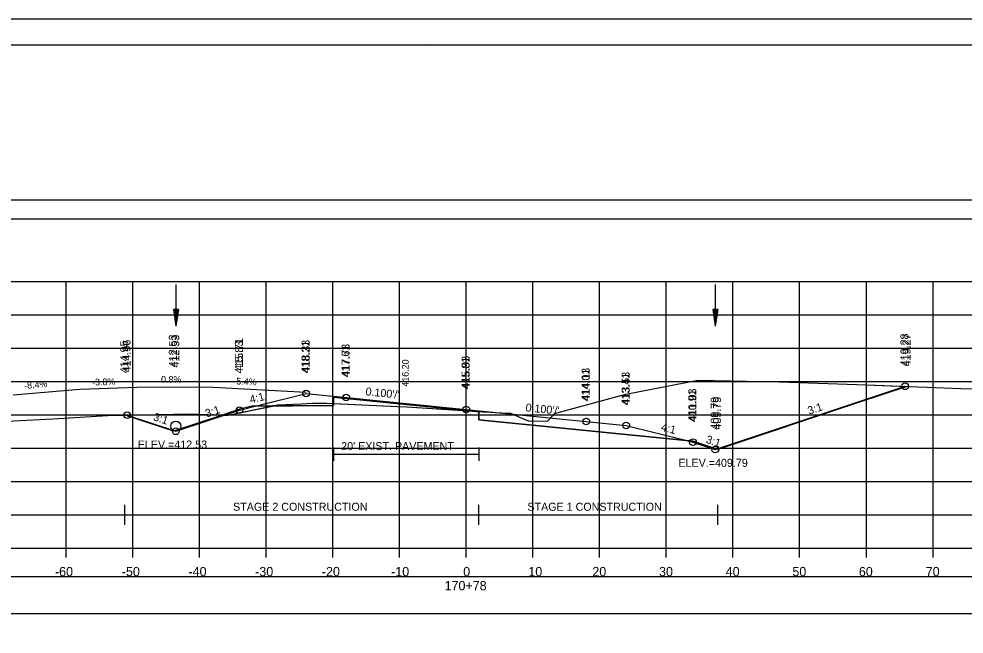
# Model space of a CAD drawing. Extents: x 1376273 to 1384221, y 378927 to 384592.
# Drawn here: x 1378523.5 to 1378665.3, y 381299.6 to 381391.9 of the extents above; entities that cross this region are included whole.
import ezdxf

# ---------------------------------------------------------------- set-up
doc = ezdxf.new("R2010")
doc.units = 0
for name, color, linetype in [('R_Alt Surface', 7, 'Continuous'), ('R_Axis', 7, 'Continuous'), ('R_Axis Annot', 7, 'Continuous'), ('R_Border', 7, 'Continuous'), ('R_Border Notes', 7, 'Continuous'), ('R_Contours', 7, 'Continuous'), ('R_Dimension', 7, 'Continuous'), ('R_Drive', 7, 'Continuous'), ('R_Exist Surface', 7, 'Continuous'), ('R_Fin Surface', 7, 'Continuous'), ('R_Grid', 7, 'Continuous'), ('R_No Plot', 7, 'Continuous'), ('R_Water', 7, 'Continuous'), ('R_Xsect Elev', 7, 'Continuous'), ('R_Xsect Slope', 7, 'Continuous'), ('T_Detection Zones', 7, 'Continuous')]:
    doc.layers.add(name, color=color, linetype=linetype)

msp = doc.modelspace()

# ---------------------------------------------------------------- linework, layer by layer
at = {"layer": 'R_Alt Surface'}
for points in [[(1378559.2, 381333.86), (1378570.72, 381333.98), (1378570.73, 381335.14), (1378590.64, 381333.15), (1378592.53, 381332.96), (1378592.54, 381331.8), (1378623.51, 381328.7)], [(1378570.73, 381327.61), (1378570.73, 381325.61)], [(1378592.53, 381327.61), (1378592.53, 381325.61)], [(1378570.73, 381326.61), (1378592.53, 381326.61)]]:
    msp.add_lwpolyline(points, dxfattribs=at)
at = {"layer": 'R_Axis'}
for p, q in [((1378440.64, 381312.51), (1378740.64, 381312.51)), ((1378530.64, 381311.11), (1378530.64, 381312.51)), ((1378540.64, 381311.11), (1378540.64, 381312.51)), ((1378550.64, 381311.11), (1378550.64, 381312.51)), ((1378560.64, 381311.11), (1378560.64, 381312.51)), ((1378570.64, 381311.11), (1378570.64, 381312.51)), ((1378580.64, 381311.11), (1378580.64, 381312.51)), ((1378590.64, 381311.11), (1378590.64, 381312.51)), ((1378600.64, 381311.11), (1378600.64, 381312.51)), ((1378610.64, 381311.11), (1378610.64, 381312.51)), ((1378620.64, 381311.11), (1378620.64, 381312.51)), ((1378630.64, 381311.11), (1378630.64, 381312.51)), ((1378640.64, 381311.11), (1378640.64, 381312.51)), ((1378650.64, 381311.11), (1378650.64, 381312.51)), ((1378660.64, 381311.11), (1378660.64, 381312.51))]:
    msp.add_line(p, q, dxfattribs=at)
at = {"layer": 'R_Axis Annot'}
for points in [[(1378439.67, 381361.89), (1378741.48, 381361.89), (1378741.48, 381364.71), (1378439.67, 381364.71)], [(1378439.67, 381302.71), (1378741.48, 381302.71), (1378741.48, 381308.24), (1378439.67, 381308.24)]]:
    msp.add_lwpolyline(points, close=True, dxfattribs=at)
at = {"layer": 'R_Border'}
for p, q in [((1378432.64, 381387.97), (1378748.82, 381387.97)), ((1378585.16, 381387.71), (1378585.16, 381387.71)), ((1378585.16, 381387.71), (1378585.16, 381387.71))]:
    msp.add_line(p, q, dxfattribs=at)
at = {"layer": 'R_Contours'}
msp.add_lwpolyline([(1378592.53, 381333.02), (1378593.11, 381332.98), (1378593.53, 381332.95), (1378593.53, 381332.95), (1378595.74, 381332.81), (1378595.95, 381332.8), (1378597.27, 381332.75), (1378598.87, 381332.04), (1378599.91, 381331.59), (1378600.07, 381331.59), (1378602.84, 381331.56), (1378602.95, 381331.69), (1378603.88, 381332.73), (1378614.58, 381335.62), (1378625.38, 381337.71), (1378637.6, 381337.44), (1378650.65, 381337.01), (1378656.78, 381336.78), (1378649.46, 381334.34), (1378628.36, 381327.3), (1378628.35, 381327.3), (1378624.64, 381328.54), (1378624.63, 381328.54), (1378624.62, 381328.54), (1378592.54, 381331.75)], close=True, dxfattribs=at)
at = {"layer": 'R_Dimension'}
for p, q in [((1378539.45, 381316.03), (1378539.45, 381319.03)), ((1378592.53, 381316.03), (1378592.53, 381319.03)), ((1378628.36, 381316.03), (1378628.36, 381319.03)), ((1378539.45, 381317.53), (1378628.36, 381317.53))]:
    msp.add_line(p, q, dxfattribs=at)
at = {"layer": 'R_Drive'}
for p, q in [((1378532.66, 381336.29), (1378522.7, 381335.44)), ((1378542.66, 381336.67), (1378532.66, 381336.29)), ((1378552.66, 381336.59), (1378542.66, 381336.67)), ((1378566.64, 381335.84), (1378552.66, 381336.59))]:
    msp.add_line(p, q, dxfattribs=at)
at = {"layer": 'R_Exist Surface'}
msp.add_lwpolyline([(1378520.85, 381331.49), (1378528.61, 381331.93), (1378536.82, 381332.41), (1378546.76, 381332.61), (1378548.88, 381332.64), (1378550.44, 381332.62), (1378554.87, 381332.44), (1378554.87, 381332.44), (1378561.82, 381333.88), (1378562.37, 381334.01), (1378565.9, 381334.17), (1378567.48, 381334.25), (1378567.58, 381334.25), (1378569.73, 381334.24), (1378580.33, 381333.77), (1378581.7, 381333.71), (1378593.11, 381332.98), (1378593.53, 381332.95), (1378593.53, 381332.95), (1378595.74, 381332.81), (1378595.95, 381332.8), (1378597.27, 381332.75), (1378598.87, 381332.04), (1378599.91, 381331.59), (1378600.07, 381331.59), (1378602.84, 381331.56), (1378602.95, 381331.69), (1378603.88, 381332.73), (1378614.58, 381335.62), (1378625.38, 381337.71), (1378637.6, 381337.44), (1378650.65, 381337.01), (1378664.85, 381336.48), (1378674.4, 381336.28)], dxfattribs=at)
at = {"layer": 'R_Fin Surface'}
msp.add_lwpolyline([(1378539.79, 381332.47), (1378547.09, 381330.04), (1378556.64, 381333.22), (1378559.2, 381333.86), (1378566.64, 381335.72), (1378572.64, 381335.12), (1378590.64, 381333.32), (1378608.64, 381331.52), (1378614.64, 381330.92), (1378623.51, 381328.7), (1378624.64, 381328.42), (1378627.99, 381327.3), (1378649.12, 381334.35), (1378656.46, 381336.79)], dxfattribs=at)
at = {"layer": 'R_Grid'}
for p, q in [((1378440.64, 381352.51), (1378740.64, 381352.51)), ((1378530.64, 381312.51), (1378530.64, 381352.51)), ((1378540.64, 381312.51), (1378540.64, 381352.51)), ((1378550.64, 381312.51), (1378550.64, 381352.51)), ((1378560.64, 381312.51), (1378560.64, 381352.51)), ((1378570.64, 381312.51), (1378570.64, 381352.51)), ((1378580.64, 381312.51), (1378580.64, 381352.51)), ((1378590.64, 381312.51), (1378590.64, 381352.51)), ((1378600.64, 381312.51), (1378600.64, 381352.51)), ((1378610.64, 381312.51), (1378610.64, 381352.51)), ((1378620.64, 381312.51), (1378620.64, 381352.51)), ((1378630.64, 381312.51), (1378630.64, 381352.51)), ((1378640.64, 381312.51), (1378640.64, 381352.51)), ((1378650.64, 381312.51), (1378650.64, 381352.51)), ((1378660.64, 381312.51), (1378660.64, 381352.51)), ((1378440.64, 381347.51), (1378740.64, 381347.51)), ((1378440.64, 381342.51), (1378740.64, 381342.51)), ((1378440.64, 381337.51), (1378740.64, 381337.51)), ((1378440.64, 381332.51), (1378740.64, 381332.51)), ((1378440.64, 381327.51), (1378740.64, 381327.51)), ((1378440.64, 381322.51), (1378740.64, 381322.51)), ((1378440.64, 381317.51), (1378740.64, 381317.51)), ((1378440.64, 381312.51), (1378740.64, 381312.51))]:
    msp.add_line(p, q, dxfattribs=at)
at = {"layer": 'R_No Plot'}
msp.add_line((1378420.24, 381391.86), (1378753.57, 381391.86), dxfattribs=at)
for points in [[(1378420.23, 381391.86), (1378753.57, 381391.86), (1378753.57, 381178.53), (1378420.23, 381178.53)], [(1378666.56, 381387.97), (1378666.56, 381378.09), (1378702.29, 381378.09), (1378702.29, 381375.17), (1378725.49, 381375.17), (1378725.49, 381350.84), (1378748.82, 381350.84), (1378748.82, 381182.51), (1378432.64, 381182.51), (1378432.64, 381387.97)]]:
    msp.add_lwpolyline(points, close=True, dxfattribs=at)
msp.add_lwpolyline([(1378558.5, 381333.81), (1378570.72, 381333.93), (1378570.73, 381335.26), (1378590.64, 381333.27), (1378592.53, 381333.08), (1378592.54, 381331.75), (1378624.62, 381328.54)], dxfattribs=at)
for centre in [(1378656.46, 381336.79), (1378566.64, 381335.72), (1378572.64, 381335.12), (1378539.79, 381332.47), (1378556.64, 381333.22), (1378590.64, 381333.32), (1378608.64, 381331.52), (1378614.64, 381330.92), (1378547.09, 381330.04), (1378547.09, 381330.04), (1378624.64, 381328.42), (1378627.99, 381327.3), (1378627.99, 381327.3)]:
    msp.add_circle(centre, 0.5, dxfattribs=at)
at = {"layer": 'R_Water'}
for p, q in [((1378547.09, 381352.04), (1378547.09, 381345.79)), ((1378627.99, 381352.04), (1378627.99, 381345.79)), ((1378546.72, 381348.29), (1378547.09, 381345.79)), ((1378547.47, 381348.29), (1378546.72, 381348.29)), ((1378546.78, 381348.29), (1378547.09, 381346.21)), ((1378546.84, 381348.29), (1378547.09, 381346.64)), ((1378546.9, 381348.29), (1378547.09, 381347.05)), ((1378546.97, 381348.29), (1378547.09, 381347.48)), ((1378547.03, 381348.29), (1378547.09, 381347.89)), ((1378547.47, 381348.29), (1378547.09, 381345.79)), ((1378547.21, 381348.29), (1378547.09, 381347.48)), ((1378547.34, 381348.29), (1378547.09, 381346.64)), ((1378547.4, 381348.29), (1378547.09, 381346.21)), ((1378547.28, 381348.29), (1378547.09, 381347.05)), ((1378547.15, 381348.29), (1378547.09, 381347.89)), ((1378627.61, 381348.29), (1378627.99, 381345.79)), ((1378628.36, 381348.29), (1378627.61, 381348.29)), ((1378627.68, 381348.29), (1378627.99, 381346.21)), ((1378627.74, 381348.29), (1378627.99, 381346.64)), ((1378627.8, 381348.29), (1378627.99, 381347.05)), ((1378627.87, 381348.29), (1378627.99, 381347.48)), ((1378627.93, 381348.29), (1378627.99, 381347.89)), ((1378628.36, 381348.29), (1378627.99, 381345.79)), ((1378628.11, 381348.29), (1378627.99, 381347.48)), ((1378628.24, 381348.29), (1378627.99, 381346.64)), ((1378628.3, 381348.29), (1378627.99, 381346.21)), ((1378628.18, 381348.29), (1378627.99, 381347.05)), ((1378628.05, 381348.29), (1378627.99, 381347.89))]:
    msp.add_line(p, q, dxfattribs=at)
msp.add_circle((1378547.07, 381330.81), 0.75, dxfattribs=at)
at = {"layer": 'T_Detection Zones'}
for points in [[(1378561.61, 381333.84), (1378561.82, 381333.88), (1378562.37, 381334.01), (1378565.9, 381334.17), (1378567.48, 381334.25), (1378567.58, 381334.25), (1378569.73, 381334.24), (1378570.72, 381334.2), (1378570.72, 381333.93)], [(1378570.72, 381334.2), (1378580.33, 381333.77), (1378581.7, 381333.71), (1378592.53, 381333.02), (1378592.53, 381333.08), (1378590.64, 381333.27), (1378570.73, 381335.26)], [(1378554.03, 381332.47), (1378554.87, 381332.44), (1378561.61, 381333.84), (1378558.5, 381333.81), (1378557.7, 381333.61), (1378556.64, 381333.34)], [(1378539.45, 381332.46), (1378546.76, 381332.61), (1378548.88, 381332.64), (1378550.44, 381332.62), (1378554.03, 381332.47), (1378546.73, 381330.04), (1378540.97, 381331.96), (1378539.45, 381332.46)]]:
    msp.add_lwpolyline(points, close=True, dxfattribs=at)

# ---------------------------------------------------------------- texts
at = {"layer": 'R_Alt Surface'}
msp.add_text("20' EXIST. PAVEMENT", height=1.2, dxfattribs=at).set_placement((1378571.88, 381327.22))
at = {"layer": 'R_Axis Annot'}
for s, p in [('-60', (1378528.95, 381308.31)), ('-50', (1378538.98, 381308.31)), ('-40', (1378548.98, 381308.31)), ('-30', (1378558.98, 381308.31)), ('-20', (1378568.98, 381308.31)), ('-10', (1378579.37, 381308.31)), ('0', (1378590.18, 381308.31)), ('10', (1378599.95, 381308.31)), ('20', (1378609.55, 381308.31)), ('30', (1378619.55, 381308.31)), ('40', (1378629.55, 381308.31)), ('50', (1378639.55, 381308.31)), ('60', (1378649.52, 381308.31)), ('70', (1378659.55, 381308.31)), ('170+78', (1378587.39, 381306.21))]:
    msp.add_text(s, height=1.4, dxfattribs=at).set_placement(p)
at = {"layer": 'R_Border Notes'}
for s, p in [('ELEV.=412.53', (1378541.37, 381327.46)), ('ELEV.=409.79', (1378622.46, 381324.72))]:
    msp.add_text(s, height=1.2, dxfattribs=at).set_placement(p)
at = {"layer": 'R_Dimension'}
for s, p in [('STAGE 2 CONSTRUCTION', (1378555.67, 381318.13)), ('STAGE 1 CONSTRUCTION', (1378599.81, 381318.13))]:
    msp.add_text(s, height=1.2, dxfattribs=at).set_placement(p)
at = {"layer": 'R_Drive'}
for s, rotation, p in [('-8.4%', 4.8254, (1378524.37, 381336.39)), ('-3.8%', 2.1914, (1378534.53, 381336.89)), ('0.8%', 359.5574, (1378544.86, 381337.34)), ('5.4%', 356.9234, (1378556.12, 381337.08))]:
    msp.add_text(s, height=1, rotation=rotation, dxfattribs=at).set_placement(p)
at = {"layer": 'R_No Plot'}
for s, p in [('412.53', (1378547.23, 381339.65)), ('419.27', (1378657.28, 381339.78)), ('414.95', (1378539.95, 381338.75)), ('415.83', (1378557.14, 381338.71)), ('418.33', (1378567.14, 381338.84)), ('417.73', (1378573.14, 381338.24)), ('415.93', (1378591.14, 381336.44)), ('414.13', (1378609.14, 381334.64)), ('413.53', (1378615.14, 381334.04)), ('411.03', (1378625.14, 381331.54)), ('409.79', (1378628.85, 381330.3))]:
    msp.add_text(s, height=1.2, rotation=90, dxfattribs=at).set_placement(p)
at = {"layer": 'R_Xsect Elev'}
for s, height, p in [('412.53', 1.2, (1378547.59, 381339.6)), ('419.28', 1.2, (1378656.96, 381339.79)), ('414.96', 1.2, (1378540.29, 381338.87)), ('415.71', 1.2, (1378557.14, 381339.1)), ('418.21', 1.2, (1378567.14, 381338.72)), ('417.61', 1.2, (1378573.14, 381338.12)), ('416.20', 1, (1378582, 381336.73)), ('415.81', 1.2, (1378591.14, 381336.32)), ('414.01', 1.2, (1378609.14, 381334.52)), ('413.41', 1.2, (1378615.14, 381333.92)), ('410.91', 1.2, (1378625.14, 381331.42)), ('409.79', 1.2, (1378628.49, 381330.3))]:
    msp.add_text(s, height=height, rotation=90, dxfattribs=at).set_placement(p)
at = {"layer": 'R_Xsect Slope'}
for s, rotation, p in [('4:1', 14.0362, (1378558.3, 381334.19)), ("0.100'/'", 354.2894, (1378575.49, 381335.44)), ("0.100'/'", 354.2894, (1378599.49, 381333.04)), ('3:1', 18.4349, (1378642.07, 381332.52)), ('3:1', 341.5651, (1378543.6, 381331.73)), ('3:1', 18.4349, (1378551.71, 381332.1)), ('4:1', 345.9638, (1378619.76, 381330.15)), ('3:1', 341.5651, (1378626.47, 381328.34))]:
    msp.add_text(s, height=1.2, rotation=rotation, dxfattribs=at).set_placement(p)

doc.saveas('drawing.dxf')
